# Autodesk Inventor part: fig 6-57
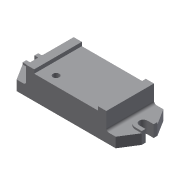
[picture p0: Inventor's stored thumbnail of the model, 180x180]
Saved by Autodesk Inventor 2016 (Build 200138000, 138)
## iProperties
Shininess: 77.0
Angle Display Precision: 2
Document Length Units: 11269
Document Angle Units: 11279
Document Time Units: 11290
Document Mass Units: 11283
Document Length Units Precision: 3
Document Angle Units Precision: 2
Created: 2001-12
Part Number: fig 6-57
Document SubType Name: Modeling
Designer: Renu Muthoo
Density: 1 g/cm^3
Material: Generic
Appearance: Default
Density: 0.0
Volumn: 0.0
Area: 0.0
PropertySet Name: Model Information
Control State: 0
Master: False
Checked Out: False
Author: Renu Muthoo
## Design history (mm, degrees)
sketch "Sketch3"
  geometry: L1 (-59.119, -24.322)-(-59.119, 19.678); L2 (-59.119, 19.678)-(-46.119, 19.678); L3 (-46.119, 19.678)-(-46.119, 13.678); L4 (-46.119, 13.678)-(55.881, 13.678); L5 (55.881, 13.678)-(55.881, 19.678); L6 (55.881, 19.678)-(68.881, 19.678); L7 (68.881, 19.678)-(68.881, -24.322); L8 (68.881, -24.322)-(-59.119, -24.322)
  constraints: 16 end point, 2 equal length
  dimensions: "d10" = 13 distance of L1.end L2.end; "d11" = 102 distance of L3.end L4.end; "d13" = 44 distance between parallel lines of L2 L8; "d14" = 6 distance of L2.end L3.end
extrude "Extrusion1" new body sketch "Sketch3" distance "d15" = 76; taper "d16" = 0 deg
sketch "Sketch4"
  geometry: L1 (0, 0)-(0, 76) reference; L2 (0, 76)-(-15, 76); L3 (-15, 76)-(-31, 50.5); L4 (-31, 50.5)-(-31, 44.5); L5 (-31, 44.5)-(-21, 44.5); L6 (-21, 31.5)-(-31, 31.5); L7 (-31, 31.5)-(-31, 25.5); L8 (-31, 25.5)-(-15, 0); L9 (-15, 0)-(0, 0); L10 (128, 76)-(0, 76) reference; L11 (0, 0)-(128, 0) reference; A1 r 6.5 centre (-21, 38) between (-21, 31.5) and (-21, 44.5)
  constraints: 16 end point, 4 equal length, 3 collinear, 3 parallel, 2 perpendicular, 2 point on circle, 2 tangent, 1 centre point
  dimensions: "d17" = 13 distance between parallel lines of L6 L5; "d18" = 25 distance of L3.end L7.end; "d19" = 10 distance of L6.start L6.end; "d20" = 15 distance of L8.end L1.start; "d21" = 16 horizontal distance of L7.end L8.end
extrude "Extrusion2" join sketch "Sketch4" distance "d22" = 16; taper "d23" = 0 deg
sketch "Sketch5"
  geometry: L1 (-159, 44.5)-(-159, 50.5) reference; L2 (-149, 44.5)-(-159, 44.5) reference; L3 (-159, 31.5)-(-149, 31.5) reference; L4 (-159, 25.5)-(-159, 31.5) reference; L5 (-159, 25.5)-(-149, 25.5); L6 (-149, 50.5)-(-159, 50.5); A1 r 6.5 centre (-149, 38) between (-149, 31.5) and (-149, 44.5) reference; A2 r 12.5 centre (-149, 38) between (-149, 25.5) and (-149, 50.5)
  constraints: 4 end point, 2 point on circle, 2 tangent, 1 centre point, 1 parallel, 1 perpendicular
extrude "Extrusion3" join sketch "Sketch5" distance "d24" = 19; taper "d25" = 0 deg
workplane "Work Plane1"
mirror "Mirror1"
fillet "Fillet1" dims "d27" = 4
sketch "Sketch6"
  geometry: L1 (0, 0)-(0, 76) reference; L2 (0, 0)-(102, 0) reference; 1 further point
  dimensions: "d28" = 20 distance from line of L1 point (20, 15); "d29" = 15 distance from line of L2 point (20, 15)
hole "Hole1" sketch "Sketch6" at (20, 15) diameter "d30" = 10; stored, may be unused: countersink angle "d34" = 82 deg, drill point angle "d36" = 118 deg; dims "d31" = 6, "d32" = 4, "d33" = 2, "d35" = 15
sketch "Sketch7"
  geometry: C1 r 5 at (20, 15) reference; 3 further points
  constraints: 4 other
body "Solid1"
other parameters: "d26" = -64
